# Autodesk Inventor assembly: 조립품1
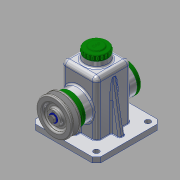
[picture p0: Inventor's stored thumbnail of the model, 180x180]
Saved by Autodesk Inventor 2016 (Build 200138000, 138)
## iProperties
Created: 2018-10
Part Number: 조립품1
Material: 일반
Document SubType Name: Assembly
Designer: user
Author: user
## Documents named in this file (14)
- C:\Users\user\Desktop\481016V1001\조립품1.iam
- C:\Users\user\Desktop\481016V1001\본체.ipt
- C:\Users\user\Desktop\481016V1001\뒤커버.ipt
- C:\Users\user\Desktop\481016V1001\앞커버.ipt
- C:\Users\user\Desktop\481016V1001\상부캡.ipt
- C:\Users\user\Desktop\481016V1001\베어링 15 x 35 x 11.ipt
- C:\Users\user\Desktop\481016V1001\오일실 15 25 7.ipt
- C:\Users\user\Desktop\481016V1001\V-벨트풀리.ipt
- C:\Users\user\Desktop\481016V1001\와셔.ipt
- C:\Users\user\Desktop\481016V1001\축.ipt
- C:\Users\user\Desktop\481016V1001\키 5 x 5 x 14.ipt
- C:\Users\user\Desktop\481016V1001\볼트 M4 x 10.ipt
- C:\Users\user\Desktop\481016V1001\멈춤링 15 x 1.ipt
- C:\Users\user\Desktop\481016V1001\볼트 M6 x 12.ipt
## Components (1 placed, 1 different names)
1. V-벨트풀리:1 — 각도:2
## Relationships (1: Angle 1)
- 각도:2 [Angle]: V-벨트풀리:1
